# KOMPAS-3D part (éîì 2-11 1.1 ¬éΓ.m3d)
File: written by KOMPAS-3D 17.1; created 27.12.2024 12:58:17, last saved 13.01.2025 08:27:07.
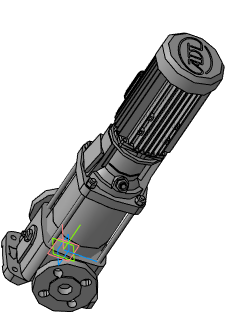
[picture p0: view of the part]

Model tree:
1. Операция без истории:4  (labels: ВМН 2-11 1.1 кВт)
